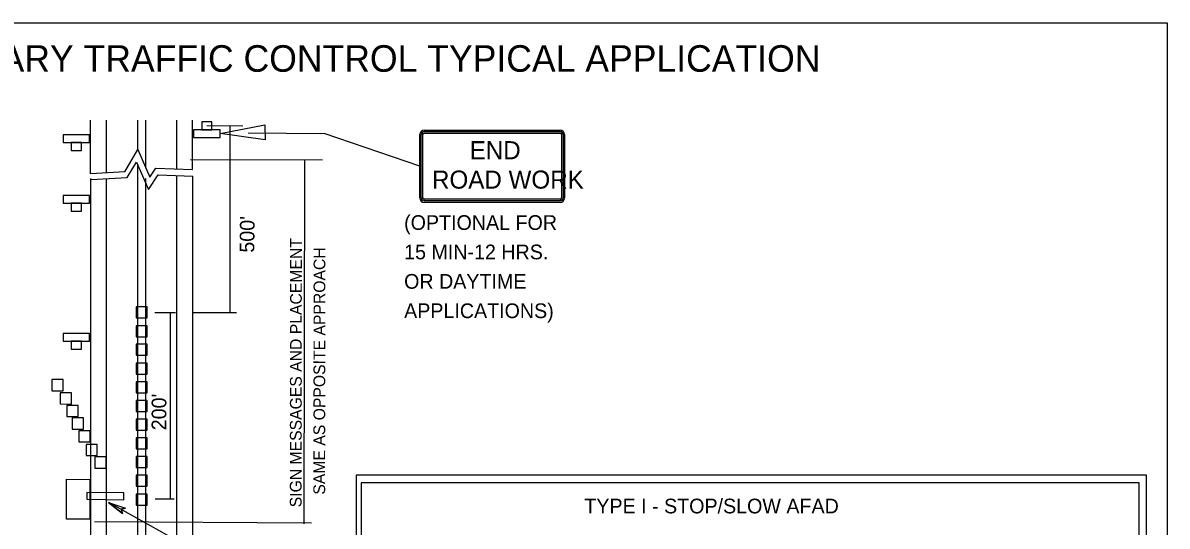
# Model space of a CAD drawing. Extents: x 21.7 to 29.1, y 5.9 to 16.2.
# Drawn here: x 24.423 to 29.094, y 14.157 to 16.211 of the extents above; entities that cross this region are included whole.
import ezdxf

# ---------------------------------------------------------------- set-up
doc = ezdxf.new("R2010")
doc.units = 0
for name, color, linetype in [('BORD-LINE', 7, 'Continuous'), ('C-SIGN-FACE-N', 7, 'Continuous'), ('DETL-DIMS', 7, 'Continuous'), ('DETL-LINE', 7, 'Continuous'), ('DETL-NOTE', 7, 'Continuous'), ('DETL-TITL', 7, 'Continuous')]:
    doc.layers.add(name, color=color, linetype=linetype)

msp = doc.modelspace()

# ---------------------------------------------------------------- linework, layer by layer
at = {"layer": 'BORD-LINE'}
msp.add_lwpolyline([(21.7194, 16.2106), (29.0936, 16.2106), (29.0936, 5.8575), (21.7194, 5.8575)], close=True, dxfattribs=at)
at = {"layer": 'C-SIGN-FACE-N'}
for p, q in [((26.0435, 15.4963), (26.0435, 15.755)), ((26.0494, 15.4963), (26.0494, 15.755)), ((26.0559, 15.4963), (26.0559, 15.755)), ((26.0618, 15.7733), (26.6157, 15.7733)), ((26.0618, 15.7733), (26.6157, 15.7733)), ((26.0618, 15.7674), (26.6157, 15.7674)), ((26.0618, 15.7609), (26.6157, 15.7609)), ((26.6216, 15.755), (26.6216, 15.4963)), ((26.6281, 15.755), (26.6281, 15.4963)), ((26.634, 15.755), (26.634, 15.4963)), ((26.6157, 15.4904), (26.0618, 15.4904)), ((26.6157, 15.4839), (26.0618, 15.4839)), ((26.6157, 15.478), (26.0618, 15.478))]:
    msp.add_line(p, q, dxfattribs=at)
for centre, radius, start, end in [((26.062, 15.7548), 0.0185, 90, 180), ((26.062, 15.7548), 0.0123, 90, 180), ((26.062, 15.7548), 0.00615, 90, 180), ((26.6156, 15.7548), 0.0185, 360, 90), ((26.6156, 15.7548), 0.0123, 360, 90), ((26.6156, 15.7548), 0.00615, 360, 90), ((26.062, 15.4965), 0.0185, 180, 270), ((26.062, 15.4965), 0.0123, 180, 270), ((26.062, 15.4965), 0.00615, 180, 270), ((26.6156, 15.4965), 0.0185, 270, 360), ((26.6156, 15.4965), 0.0123, 270, 360), ((26.6156, 15.4965), 0.00615, 270, 360)]:
    msp.add_arc(centre, radius, start, end, dxfattribs=at)
at = {"layer": 'DETL-DIMS'}
for p, q in [((25.1745, 15.7917), (25.3214, 15.7898)), ((25.268, 15.7904), (25.268, 15.0287)), ((25.343, 15.7614), (25.6524, 15.7591)), ((26.0435, 15.6257), (25.6524, 15.7591)), ((25.1076, 15.6525), (25.6465, 15.6511)), ((25.5715, 14.1665), (25.5744, 15.6497)), ((24.9619, 15.0285), (25.0456, 15.0286)), ((25.0244, 15.0288), (25.0244, 14.268)), ((25.1176, 15.0285), (25.295, 15.0287)), ((24.7733, 14.2537), (24.8294, 14.2076)), ((24.7733, 14.2537), (24.8418, 14.2296)), ((25.0466, 14.101), (24.7747, 14.2533)), ((24.9638, 14.2681), (25.0414, 14.2679)), ((24.8239, 14.2252), (24.8418, 14.2296)), ((24.8294, 14.2076), (24.8239, 14.2252)), ((25.6013, 14.1682), (24.7156, 14.1745))]:
    msp.add_line(p, q, dxfattribs=at)
for points in [[(25.4115, 15.7942), (25.4128, 15.7327), (25.2284, 15.7586)], [(24.8294, 14.2076), (24.7733, 14.2537), (24.8418, 14.2296), (24.8239, 14.2252)]]:
    msp.add_lwpolyline(points, close=True, dxfattribs=at)
at = {"layer": 'DETL-LINE'}
for p, q in [((24.6998, 15.594), (24.6998, 15.8136)), ((24.7651, 15.5985), (24.7651, 15.8136)), ((24.8927, 15.6932), (24.8927, 15.8136)), ((24.9252, 15.618), (24.9252, 15.8136)), ((24.9252, 15.6189), (24.9252, 15.8136)), ((25.0521, 15.6149), (25.0521, 15.8136)), ((25.1159, 15.612), (25.1159, 15.8136)), ((24.839, 15.6029), (24.7008, 15.594)), ((24.8927, 7.7401), (24.8927, 15.6283)), ((24.966, 15.6179), (25.1159, 15.612)), ((24.7011, 9.2959), (24.7011, 15.5751)), ((24.7651, 9.2959), (24.7651, 15.5751)), ((24.893, 9.2959), (24.893, 15.5751)), ((24.9252, 9.2959), (24.9252, 15.5751)), ((24.9252, 7.7401), (24.9252, 15.5547)), ((25.0521, 15.5751), (25.0521, 15.5874)), ((25.0521, 15.5874), (25.0521, 15.5874)), ((25.0521, 11.2067), (25.0521, 15.5751)), ((25.1164, 15.5751), (25.1164, 15.5845)), ((25.1164, 11.2067), (25.1164, 15.5751))]:
    msp.add_line(p, q, dxfattribs=at)
for points in [[(25.1538, 15.774), (25.1951, 15.774), (25.1951, 15.8067), (25.1538, 15.8067)], [(24.6956, 15.7228), (24.6956, 15.7537), (24.5874, 15.7537), (24.5874, 15.7228)], [(25.1202, 15.774), (25.1202, 15.7431), (25.2284, 15.7431), (25.2284, 15.774)], [(24.662, 15.7228), (24.6207, 15.7228), (24.6207, 15.6901), (24.662, 15.6901)], [(24.6956, 15.4745), (24.6956, 15.5054), (24.5874, 15.5054), (24.5874, 15.4745)], [(24.662, 15.4745), (24.6207, 15.4745), (24.6207, 15.4418), (24.662, 15.4418)], [(24.8857, 15.0063), (24.9305, 15.0063), (24.9305, 15.0511), (24.8857, 15.0511)], [(24.8857, 14.9297), (24.9305, 14.9297), (24.9305, 14.9745), (24.8857, 14.9745)], [(24.6957, 14.9121), (24.6957, 14.943), (24.5875, 14.943), (24.5875, 14.9121)], [(24.6621, 14.9121), (24.6208, 14.9121), (24.6208, 14.8794), (24.6621, 14.8794)], [(24.8857, 14.8539), (24.9305, 14.8539), (24.9305, 14.8987), (24.8857, 14.8987)], [(24.8857, 14.7773), (24.9305, 14.7773), (24.9305, 14.8221), (24.8857, 14.8221)], [(24.5421, 14.7546), (24.542, 14.7088), (24.5879, 14.7086), (24.5879, 14.7544)], [(24.8857, 14.7007), (24.9305, 14.7007), (24.9305, 14.7455), (24.8857, 14.7455)], [(24.5759, 14.7009), (24.5757, 14.6551), (24.6216, 14.6549), (24.6216, 14.7007)], [(24.8857, 14.625), (24.9305, 14.625), (24.9305, 14.6698), (24.8857, 14.6698)], [(24.6029, 14.6495), (24.6027, 14.6036), (24.6486, 14.6035), (24.6487, 14.6493)], [(24.6245, 14.5989), (24.6244, 14.553), (24.6702, 14.5529), (24.6703, 14.5987)], [(24.8857, 14.5484), (24.9305, 14.5484), (24.9305, 14.5932), (24.8857, 14.5932)], [(24.6521, 14.546), (24.652, 14.5001), (24.6979, 14.5), (24.6979, 14.5458)], [(24.6813, 14.4902), (24.6812, 14.4443), (24.727, 14.4442), (24.7271, 14.49)], [(24.8857, 14.4717), (24.9305, 14.4717), (24.9305, 14.5165), (24.8857, 14.5165)], [(24.7168, 14.4392), (24.7167, 14.3933), (24.7626, 14.3932), (24.7626, 14.439)], [(24.8857, 14.396), (24.9305, 14.396), (24.9305, 14.4408), (24.8857, 14.4408)], [(24.6972, 14.3473), (24.6963, 14.1848), (24.6007, 14.1853), (24.6016, 14.3478)], [(24.8857, 14.3194), (24.9305, 14.3194), (24.9305, 14.3642), (24.8857, 14.3642)], [(25.7831, 11.5962), (29.0092, 11.5962), (29.0092, 14.3652), (25.7831, 14.3652)], [(24.6845, 14.2664), (24.835, 14.2644), (24.8353, 14.2926), (24.6849, 14.2945)], [(25.8041, 13.0169), (28.9793, 13.0169), (28.9793, 14.3329), (25.8041, 14.3329)], [(24.8857, 14.2428), (24.9305, 14.2427), (24.9307, 14.2875), (24.8859, 14.2876)], [(24.8857, 14.2428), (24.9305, 14.2428), (24.9305, 14.2876), (24.8857, 14.2876)]]:
    msp.add_lwpolyline(points, close=True, dxfattribs=at)
for points in [[(24.839, 15.6029), (24.8927, 15.6932), (24.942, 15.5805), (24.966, 15.6179)], [(24.7014, 15.5712), (24.8488, 15.5792), (24.8866, 15.6427), (24.9358, 15.5299), (24.9748, 15.5908), (25.1168, 15.5844)]]:
    msp.add_lwpolyline(points, dxfattribs=at)

# ---------------------------------------------------------------- texts
at = {"layer": 'C-SIGN-FACE-N'}
for s, p in [('END', (26.2467, 15.654)), ('ROAD WORK', (26.0931, 15.5341))]:
    msp.add_text(s, height=0.07381, rotation=360, dxfattribs=at).set_placement(p)
at = {"layer": 'DETL-NOTE'}
for s, height, rotation, p in [("500'", 0.06, 89.1758, (25.3675, 15.2724)), ('SIGN MESSAGES AND PLACEMENT ', 0.048, 89.9409, (25.5609, 14.2335)), ('SAME AS OPPOSITE APPROACH', 0.048, 89.9409, (25.6569, 14.2851)), ("200'", 0.06, 89.8604, (25.0086, 14.5478))]:
    msp.add_text(s, height=height, rotation=rotation, dxfattribs=at).set_placement(p)
for s, p in [('(OPTIONAL FOR', (25.9793, 15.3656)), ('15 MIN-12 HRS. ', (25.9793, 15.2456)), ('OR DAYTIME', (25.9793, 15.1256)), ('APPLICATIONS)', (25.9793, 15.0056)), ('TYPE I - STOP/SLOW AFAD', (26.7149, 14.2086))]:
    msp.add_text(s, height=0.06, dxfattribs=at).set_placement(p)
at = {"layer": 'DETL-TITL'}
msp.add_text('TEMPORARY TRAFFIC CONTROL TYPICAL APPLICATION', height=0.10852, dxfattribs=at).set_placement((23.7115, 16.011))

doc.saveas('drawing.dxf')
